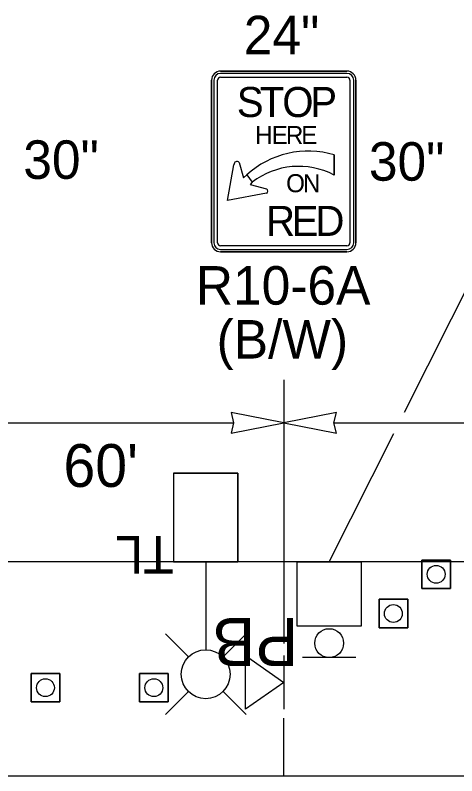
# Model space of a CAD drawing. Extents: x 99982 to 100176, y 99905 to 100011.
# Drawn here: x 100064.999 to 100065.824, y 99917.539 to 99918.961 of the extents above; entities that cross this region are included whole.
import ezdxf

# ---------------------------------------------------------------- set-up
doc = ezdxf.new("R2010")
doc.units = 0
for name, color, linetype in [('RD_ED_ShoulderPavedEdge', 7, 'Continuous'), ('RD_MK_LineEdgeWhite', 7, 'Continuous'), ('TR_SN_ConstructionSigns', 7, 'Continuous'), ('TR_WZ_PortableLightStandard', 7, 'Continuous'), ('TR_WZ_PortableSignMountBlk-Wht', 7, 'Continuous'), ('TR_WZ_Sign', 7, 'Continuous'), ('TR_WZ_TempSignal', 7, 'Continuous'), ('TR_WZ_TrafficCone', 7, 'Continuous'), ('TR_WZ_WorkZoneDetails', 7, 'Continuous'), ('TR_WZ_WorkZoneTextCurrent', 7, 'Continuous')]:
    doc.layers.add(name, color=color, linetype=linetype)

msp = doc.modelspace()

# ---------------------------------------------------------------- linework, layer by layer
at = {"layer": 'RD_ED_ShoulderPavedEdge'}
msp.add_line((100075.6424, 99917.9393), (100060.3, 99917.9393), dxfattribs=at)
at = {"layer": 'RD_MK_LineEdgeWhite'}
msp.add_line((100064.8112, 99917.5393), (100075.6425, 99917.5393), dxfattribs=at)
at = {"layer": 'TR_SN_ConstructionSigns'}
for p, q in [((100065.6189, 99918.8565), (100065.3827, 99918.8565)), ((100065.3827, 99918.8565), (100065.6189, 99918.8565)), ((100065.6189, 99918.8565), (100065.3827, 99918.8565)), ((100065.3827, 99918.8565), (100065.6189, 99918.8565)), ((100065.3658, 99918.8396), (100065.3658, 99918.5358)), ((100065.3658, 99918.5358), (100065.3658, 99918.8396)), ((100065.3658, 99918.8396), (100065.3658, 99918.5358)), ((100065.3658, 99918.5358), (100065.3658, 99918.8396)), ((100065.37, 99918.8396), (100065.37, 99918.5358)), ((100065.377, 99918.5358), (100065.377, 99918.8396)), ((100065.6189, 99918.8522), (100065.3827, 99918.8522)), ((100065.3827, 99918.8452), (100065.6189, 99918.8452)), ((100065.6245, 99918.8396), (100065.6245, 99918.5358)), ((100065.6316, 99918.5358), (100065.6316, 99918.8396)), ((100065.6358, 99918.5358), (100065.6358, 99918.8396)), ((100065.6358, 99918.8396), (100065.6358, 99918.5358)), ((100065.6358, 99918.5358), (100065.6358, 99918.8396)), ((100065.6358, 99918.8396), (100065.6358, 99918.5358)), ((100065.5953, 99918.7001), (100065.5949, 99918.6623)), ((100065.5949, 99918.6623), (100065.5953, 99918.7001)), ((100065.4173, 99918.6859), (100065.4258, 99918.6568)), ((100065.3953, 99918.6146), (100065.4076, 99918.6816)), ((100065.4258, 99918.6568), (100065.4315, 99918.6625)), ((100065.4315, 99918.6625), (100065.442, 99918.6491)), ((100065.4315, 99918.6625), (100065.442, 99918.6491)), ((100065.442, 99918.6491), (100065.4377, 99918.6448)), ((100065.4377, 99918.6448), (100065.4685, 99918.6365)), ((100065.4683, 99918.6281), (100065.3953, 99918.6146)), ((100065.6189, 99918.5302), (100065.3827, 99918.5302)), ((100065.3827, 99918.5232), (100065.6189, 99918.5232)), ((100065.3827, 99918.519), (100065.6189, 99918.519)), ((100065.6189, 99918.519), (100065.3827, 99918.519)), ((100065.3827, 99918.519), (100065.6189, 99918.519)), ((100065.6189, 99918.519), (100065.3827, 99918.519))]:
    msp.add_line(p, q, dxfattribs=at)
for centre, radius, start, end in [((100065.3827, 99918.8396), 0.0169, 90, 180), ((100065.3827, 99918.8396), 0.0169, 90, 180), ((100065.3827, 99918.8396), 0.0169, 90, 180), ((100065.3827, 99918.8396), 0.0169, 90, 180), ((100065.6189, 99918.8396), 0.0169, 0, 90), ((100065.6189, 99918.8396), 0.0169, 0, 90), ((100065.6189, 99918.8396), 0.0169, 0, 90), ((100065.6189, 99918.8396), 0.0169, 0, 90), ((100065.3827, 99918.8396), 0.0127, 90, 180), ((100065.3827, 99918.8396), 0.00562, 90, 180), ((100065.6189, 99918.8396), 0.0127, 0, 90), ((100065.6189, 99918.8396), 0.00562, 0, 90), ((100065.5469, 99918.5352), 0.1718, 73.6434, 132.2131), ((100065.5469, 99918.5352), 0.1718, 73.6434, 132.2131), ((100065.5288, 99918.5358), 0.1427, 62.4149, 127.4769), ((100065.5288, 99918.5358), 0.1427, 62.4149, 127.4769), ((100065.3827, 99918.5358), 0.0169, 180, 270), ((100065.3827, 99918.5358), 0.0169, 180, 270), ((100065.3827, 99918.5358), 0.0169, 180, 270), ((100065.3827, 99918.5358), 0.0169, 180, 270), ((100065.3827, 99918.5358), 0.0127, 180, 270), ((100065.3827, 99918.5358), 0.00562, 180, 270), ((100065.6189, 99918.5358), 0.0169, 270, 0), ((100065.6189, 99918.5358), 0.0169, 270, 0), ((100065.6189, 99918.5358), 0.0169, 270, 0), ((100065.6189, 99918.5358), 0.0127, 270, 0), ((100065.6189, 99918.5358), 0.00562, 270, 0), ((100065.6189, 99918.5358), 0.0169, 270, 0)]:
    msp.add_arc(centre, radius, start, end, dxfattribs=at)
for centre, major_axis, ratio, start_param, end_param in [((100065.4134, 99918.6817), (-0.00583, -0.00008), 0.989437, 3.962549, 6.283185), ((100065.4664, 99918.6324), (-0.00414, 0.00215), 0.999053, 2.490568, 4.712389)]:
    msp.add_ellipse(centre, major_axis=major_axis, ratio=ratio, start_param=start_param, end_param=end_param, dxfattribs=at)
at = {"layer": 'TR_WZ_PortableLightStandard'}
for p, q in [((100065.2948, 99918.1053), (100065.2948, 99917.9393)), ((100065.2948, 99918.1053), (100065.4148, 99918.1053)), ((100065.2948, 99918.1053), (100065.2948, 99917.9393)), ((100065.4148, 99918.1053), (100065.4148, 99917.9393)), ((100065.4148, 99917.9393), (100065.4148, 99918.1053)), ((100065.2948, 99917.9393), (100065.4148, 99917.9393)), ((100065.3548, 99917.9393), (100065.3548, 99917.7749)), ((100065.3224, 99917.7615), (100065.2794, 99917.8046)), ((100065.3872, 99917.7615), (100065.4303, 99917.8046)), ((100065.3224, 99917.6968), (100065.2794, 99917.6537)), ((100065.3872, 99917.6968), (100065.4303, 99917.6537))]:
    msp.add_line(p, q, dxfattribs=at)
for points in [[(100065.4148, 99918.1053), (100065.3548, 99918.1053), (100065.2948, 99918.1053)], [(100065.2948, 99917.9393), (100065.3548, 99917.9393), (100065.4148, 99917.9393)]]:
    msp.add_lwpolyline(points, dxfattribs=at)
msp.add_circle((100065.3548, 99917.7291), 0.0457, dxfattribs=at)
msp.add_circle((100065.3548, 99917.7291), 0.0457, dxfattribs=at)
at = {"layer": 'TR_WZ_PortableSignMountBlk-Wht'}
msp.add_line((100065.5008, 99917.764), (100065.5008, 99917.664), dxfattribs=at)
msp.add_lwpolyline([(100065.5008, 99917.714), (100065.429, 99917.664), (100065.429, 99917.764)], close=True, dxfattribs=at)
at = {"layer": 'TR_WZ_Sign'}
msp.add_line((100065.6358, 99917.7603), (100065.5358, 99917.7603), dxfattribs=at)
msp.add_circle((100065.5857, 99917.7873), 0.027, dxfattribs=at)
msp.add_circle((100065.5857, 99917.7873), 0.027, dxfattribs=at)
at = {"layer": 'TR_WZ_TempSignal'}
msp.add_lwpolyline([(100065.6458, 99917.8193), (100065.5258, 99917.8193), (100065.5258, 99917.9393), (100065.6458, 99917.9393)], close=True, dxfattribs=at)
msp.add_lwpolyline([(100065.6458, 99917.8193), (100065.5258, 99917.8193), (100065.5258, 99917.9393), (100065.6458, 99917.9393)], close=True, dxfattribs=at)
at = {"layer": 'TR_WZ_TrafficCone'}
for points in [[(100065.8125, 99917.8893), (100065.7591, 99917.8893), (100065.7591, 99917.9426), (100065.8125, 99917.9426), (100065.8125, 99917.8893)], [(100065.8125, 99917.9426), (100065.7591, 99917.9426), (100065.7591, 99917.8893), (100065.8125, 99917.8893), (100065.8125, 99917.9426)], [(100065.7325, 99917.816), (100065.6791, 99917.816), (100065.6791, 99917.8693), (100065.7325, 99917.8693), (100065.7325, 99917.816)], [(100065.7325, 99917.8693), (100065.6791, 99917.8693), (100065.6791, 99917.816), (100065.7325, 99917.816), (100065.7325, 99917.8693)], [(100065.0818, 99917.6773), (100065.0284, 99917.6773), (100065.0284, 99917.7306), (100065.0818, 99917.7306), (100065.0818, 99917.6773)], [(100065.0818, 99917.7306), (100065.0284, 99917.7306), (100065.0284, 99917.6773), (100065.0818, 99917.6773), (100065.0818, 99917.7306)], [(100065.2846, 99917.6773), (100065.2313, 99917.6773), (100065.2313, 99917.7306), (100065.2846, 99917.7306), (100065.2846, 99917.6773)], [(100065.2846, 99917.7306), (100065.2313, 99917.7306), (100065.2313, 99917.6773), (100065.2846, 99917.6773), (100065.2846, 99917.7306)]]:
    msp.add_lwpolyline(points, dxfattribs=at)
for centre in [(100065.7858, 99917.916), (100065.7058, 99917.8426), (100065.0551, 99917.704), (100065.2579, 99917.704)]:
    msp.add_circle(centre, 0.0167, dxfattribs=at)
at = {"layer": 'TR_WZ_WorkZoneDetails'}
for p, q in [((100065.7266, 99918.2193), (100065.8892, 99918.5428)), ((100065.5008, 99918.2793), (100065.5008, 99917.7869)), ((100064.9049, 99918.1993), (100065.4071, 99918.1993)), ((100065.5945, 99918.1993), (100066.8987, 99918.1993)), ((100065.5858, 99917.9393), (100065.7065, 99918.1793)), ((100065.5008, 99917.5393), (100065.5008, 99917.6469))]:
    msp.add_line(p, q, dxfattribs=at)
for points in [[(100065.5008, 99918.1993), (100065.4025, 99918.2186), (100065.4071, 99918.1993), (100065.4025, 99918.18)], [(100065.5008, 99918.1993), (100065.5991, 99918.18), (100065.5945, 99918.1993), (100065.5991, 99918.2186)]]:
    msp.add_lwpolyline(points, close=True, dxfattribs=at)

# ---------------------------------------------------------------- texts
at = {"layer": 'TR_SN_ConstructionSigns'}
for s, p in [('24"', (100065.426, 99918.888)), ('30"', (100065.0137, 99918.6551)), ('30"', (100065.66, 99918.6517)), ('R10-6A', (100065.3364, 99918.42)), ('(B/W)', (100065.3752, 99918.3192))]:
    msp.add_text(s, height=0.072, rotation=360, dxfattribs=at).set_placement(p)
for s, height, p in [('S', 0.0562, (100065.413, 99918.7707)), ('T', 0.0562, (100065.4558, 99918.7707)), ('O', 0.0562, (100065.498, 99918.7707)), ('P', 0.0562, (100065.5503, 99918.7707)), ('H', 0.0338, (100065.4471, 99918.7201)), ('E', 0.0338, (100065.4782, 99918.7201)), ('R', 0.0338, (100065.5048, 99918.7201)), ('E', 0.0338, (100065.5335, 99918.7201)), ('O', 0.0338, (100065.5052, 99918.6301)), ('N', 0.0338, (100065.5366, 99918.6301)), ('R', 0.0562, (100065.4677, 99918.5485)), ('E', 0.0562, (100065.5155, 99918.5485)), ('D', 0.0562, (100065.56, 99918.5485))]:
    msp.add_text(s, height=height, dxfattribs=at).set_placement(p)
at = {"layer": 'TR_WZ_PortableLightStandard'}
msp.add_text('TL', height=0.07, rotation=180, dxfattribs=at).set_placement((100065.2949, 99917.9873))
at = {"layer": 'TR_WZ_TempSignal'}
msp.add_text('PB', height=0.09, rotation=180, dxfattribs=at).set_placement((100065.5281, 99917.8343))
at = {"layer": 'TR_WZ_WorkZoneTextCurrent'}
msp.add_text("60'", height=0.08, dxfattribs=at).set_placement((100065.0888, 99918.0793))

doc.saveas('drawing.dxf')
